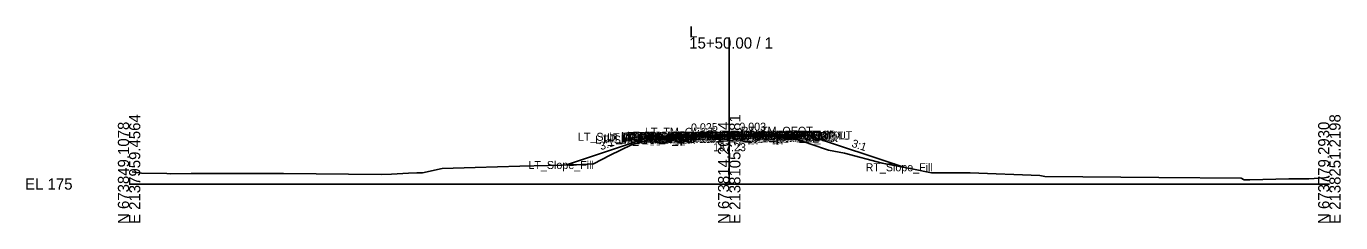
# Model space of a CAD drawing. Extents: x -26 to 5503, y -10 to 7033.
# Drawn here: x -25.7 to 302.8, y 6490.3 to 6539.5 of the extents above; entities that cross this region are included whole.
import ezdxf

# ---------------------------------------------------------------- set-up
doc = ezdxf.new("R2010")
doc.units = 0
for name, color, linetype in [('Default', 7, 'Continuous'), ('Exist CMT Pavement', 7, 'Continuous'), ('Exist Cross Section Cell', 7, 'Continuous'), ('Exist XS Center Line Elevation Label', 7, 'Continuous'), ('Exist XS Ground Line', 7, 'Continuous'), ('Prop CMT Pvmt Course 1', 7, 'Continuous'), ('Prop CMT Pvmt Course 1 Wedge', 7, 'Continuous'), ('Prop CMT Pvmt Course 2', 7, 'Continuous'), ('Prop CMT Pvmt Course 2 Wedge', 7, 'Continuous'), ('Prop CMT Pvmt Course 3', 7, 'Continuous'), ('Prop CMT Pvmt Course 3 Wedge', 7, 'Continuous'), ('Prop CMT Pvmt Surface', 7, 'Continuous'), ('Prop CMT Pvmt Surface Shoulder', 7, 'Continuous'), ('Prop CMT Pvmt Wedge Surface 1', 7, 'Continuous'), ('Prop CMT Pvmt Wedge Surface 2', 7, 'Continuous'), ('Prop CMT Pvmt Wedge Surface 3', 7, 'Continuous'), ('Prop CMT Shld Paved Course 1', 7, 'Continuous'), ('Prop CMT Shld Paved Course 2', 7, 'Continuous'), ('Prop CMT Shld Paved Course 3', 7, 'Continuous'), ('Prop CMT Slope Grass', 7, 'Continuous'), ('Prop CMT Subgrade Earthwork', 7, 'Continuous'), ('Prop XS Earthwork Shape', 7, 'Continuous'), ('Prop XS EOT Tick Mark', 7, 'Continuous'), ('Prop XS SE Text', 7, 'Continuous'), ('Prop XS Side Slope Text', 7, 'Continuous'), ('Prop XS Wedging', 7, 'Continuous')]:
    doc.layers.add(name, color=color, linetype=linetype)

msp = doc.modelspace()

# ---------------------------------------------------------------- linework, layer by layer
at = {"layer": 'Exist CMT Pavement'}
for points in [[(150, 6512.23), (148.67, 6512.21), (144, 6512.14), (139.33, 6512.06), (138, 6512.04)], [(150, 6512.23), (151.33, 6512.21), (155.98, 6512.12), (160.63, 6512.03), (161.96, 6512.01)]]:
    msp.add_lwpolyline(points, dxfattribs=at)
at = {"layer": 'Exist Cross Section Cell'}
for p, q in [((150, 6500), (150, 6536.71)), ((0, 6500), (150, 6500)), ((150, 6500), (300, 6500))]:
    msp.add_line(p, q, dxfattribs=at)
at = {"layer": 'Exist XS Ground Line'}
for p, q in [((129.99, 6511.06), (136, 6511.89)), ((136, 6511.89), (137.72, 6512.03)), ((137.72, 6512.03), (148.42, 6512.21)), ((148.42, 6512.21), (149.71, 6512.24)), ((149.71, 6512.24), (160.7, 6512.03)), ((160.7, 6512.03), (161.92, 6512.01)), ((161.92, 6512.01), (162.88, 6511.95)), ((162.88, 6511.95), (165.5, 6511.71)), ((165.5, 6511.71), (170.41, 6509.99)), ((120.28, 6507.27), (125.6, 6509.79)), ((125.6, 6509.79), (129.99, 6511.06)), ((170.41, 6509.99), (174.81, 6508.44)), ((174.81, 6508.44), (178.81, 6507.72)), ((111.8, 6504.85), (116.06, 6505.02)), ((116.06, 6505.02), (120.28, 6507.27)), ((178.81, 6507.72), (188.23, 6505.2)), ((188.23, 6505.2), (196.02, 6503.75)), ((0.73, 6503.08), (3.08, 6502.76)), ((3.08, 6502.76), (9.46, 6502.61)), ((9.46, 6502.61), (10.39, 6502.55)), ((10.39, 6502.55), (15.54, 6502.61)), ((15.54, 6502.61), (38.62, 6502.64)), ((38.62, 6502.64), (62.97, 6502.42)), ((62.97, 6502.42), (65.56, 6502.46)), ((65.56, 6502.46), (69.83, 6502.75)), ((69.83, 6502.75), (71.89, 6502.79)), ((71.89, 6502.79), (72.8, 6502.81)), ((72.8, 6502.81), (73.32, 6502.82)), ((73.32, 6502.82), (78.22, 6503.85)), ((78.22, 6503.85), (86.49, 6504.16)), ((86.49, 6504.16), (97.69, 6504.46)), ((97.69, 6504.46), (111.8, 6504.85)), ((196.02, 6503.75), (200.52, 6502.8)), ((200.52, 6502.8), (210.19, 6502.78)), ((210.19, 6502.78), (227.65, 6502.11)), ((227.65, 6502.11), (228.88, 6501.86)), ((228.88, 6501.86), (257.37, 6501.62)), ((298.77, 6501.57), (299.61, 6501.73)), ((299.61, 6501.73), (300, 6501.97)), ((257.37, 6501.62), (277.99, 6501.45)), ((277.99, 6501.45), (278.68, 6501.08)), ((278.68, 6501.08), (280.13, 6501.03)), ((280.13, 6501.03), (289.85, 6501.34)), ((289.85, 6501.34), (294.9, 6501.28)), ((294.9, 6501.28), (298.77, 6501.57))]:
    msp.add_line(p, q, dxfattribs=at)
at = {"layer": 'Prop CMT Pvmt Course 1'}
for points in [[(150, 6512.38), (138, 6512.08)], [(138, 6511.95), (150, 6512.25)], [(138, 6512.08), (138, 6511.83), (138, 6511.83), (138, 6511.95)], [(150, 6512.25), (150, 6512.38)], [(150, 6512.38), (162, 6512.34)], [(150, 6512.25), (150, 6512.38)], [(161.96, 6512.22), (150, 6512.25)], [(161.96, 6512.09), (161.96, 6512.22)], [(162, 6512.09), (161.96, 6512.09)], [(162, 6512.34), (162, 6512.09)]]:
    msp.add_lwpolyline(points, dxfattribs=at)
at = {"layer": 'Prop CMT Pvmt Course 1 Wedge'}
for points in [[(150, 6512.25), (138, 6511.95)], [(150, 6512.25), (161.96, 6512.22)]]:
    msp.add_lwpolyline(points, dxfattribs=at)
at = {"layer": 'Prop CMT Pvmt Course 2'}
for points in [[(161.96, 6511.88), (161.96, 6512.09)], [(161.96, 6512.09), (162, 6512.09)], [(162, 6511.88), (161.96, 6511.88)], [(162, 6512.09), (162, 6511.88)]]:
    msp.add_lwpolyline(points, dxfattribs=at)
at = {"layer": 'Prop CMT Pvmt Course 2 Wedge'}
for points in [[(150, 6512.13), (138, 6511.83)], [(150, 6512.13), (161.96, 6512.09)]]:
    msp.add_lwpolyline(points, dxfattribs=at)
at = {"layer": 'Prop CMT Pvmt Course 3'}
for points in [[(138, 6511.62), (138, 6511.62), (138, 6511.29), (138, 6511.29)], [(138, 6511.29), (138, 6511.62)], [(161.96, 6511.88), (162, 6511.88)], [(161.96, 6511.55), (161.96, 6511.88)], [(162, 6511.55), (161.96, 6511.55)], [(162, 6511.88), (162, 6511.55)]]:
    msp.add_lwpolyline(points, dxfattribs=at)
at = {"layer": 'Prop CMT Pvmt Course 3 Wedge'}
for points in [[(150, 6511.92), (138, 6511.62)], [(150, 6511.92), (161.96, 6511.88)]]:
    msp.add_lwpolyline(points, dxfattribs=at)
at = {"layer": 'Prop CMT Pvmt Surface'}
for points in [[(150, 6512.38), (138, 6512.08)], [(150, 6512.38), (162, 6512.34)]]:
    msp.add_lwpolyline(points, dxfattribs=at)
at = {"layer": 'Prop CMT Pvmt Surface Shoulder'}
for points in [[(138, 6512.08), (133.12, 6511.95)], [(162, 6512.34), (166.78, 6512.33)]]:
    msp.add_lwpolyline(points, dxfattribs=at)
at = {"layer": 'Prop CMT Pvmt Wedge Surface 1'}
for points in [[(150, 6512.25), (138, 6511.95)], [(138, 6511.95), (138, 6512.08)], [(138, 6512.08), (138, 6512.08)], [(150, 6512.25), (161.96, 6512.22)], [(161.96, 6512.22), (161.96, 6512.34)], [(161.96, 6512.34), (162, 6512.34)]]:
    msp.add_lwpolyline(points, dxfattribs=at)
at = {"layer": 'Prop CMT Pvmt Wedge Surface 2'}
for points in [[(150, 6512.13), (138, 6511.83)], [(138, 6511.83), (138, 6512.08)], [(138, 6511.83), (138, 6511.83)], [(150, 6512.13), (161.96, 6512.09), (162, 6512.09)], [(162, 6512.09), (162, 6512.34)]]:
    msp.add_lwpolyline(points, dxfattribs=at)
at = {"layer": 'Prop CMT Pvmt Wedge Surface 3'}
for points in [[(138, 6511.62), (138, 6512.08)], [(150, 6511.92), (138, 6511.62)], [(138, 6511.62), (138, 6511.62)], [(150, 6511.92), (161.96, 6511.88), (162, 6511.88)], [(162, 6511.88), (162, 6512.34)]]:
    msp.add_lwpolyline(points, dxfattribs=at)
at = {"layer": 'Prop CMT Shld Paved Course 1'}
for points in [[(138, 6512.08), (133.12, 6511.95), (132.87, 6511.7)], [(132.87, 6511.7), (138, 6511.83)], [(138, 6511.83), (138, 6512.08)], [(162, 6512.34), (166.78, 6512.33), (167.03, 6512.08)], [(162, 6512.09), (162, 6512.34)], [(167.03, 6512.08), (162, 6512.09)]]:
    msp.add_lwpolyline(points, dxfattribs=at)
at = {"layer": 'Prop CMT Shld Paved Course 2'}
for points in [[(138, 6511.83), (132.87, 6511.7), (132.65, 6511.48)], [(132.65, 6511.48), (138, 6511.62)], [(138, 6511.62), (138, 6511.83)], [(162, 6512.09), (167.03, 6512.08), (167.24, 6511.87)], [(162, 6511.88), (162, 6512.09)], [(167.24, 6511.87), (162, 6511.88)]]:
    msp.add_lwpolyline(points, dxfattribs=at)
at = {"layer": 'Prop CMT Shld Paved Course 3'}
for points in [[(138, 6511.62), (132.65, 6511.48)], [(138, 6511.29), (138, 6511.62)], [(162, 6511.88), (167.24, 6511.87)], [(162, 6511.55), (162, 6511.88)], [(167.57, 6511.53), (162, 6511.55)], [(167.24, 6511.87), (167.24, 6511.87)], [(167.24, 6511.87), (167.57, 6511.53)], [(132.65, 6511.48), (132.31, 6511.14)], [(132.31, 6511.14), (138, 6511.29)], [(132.65, 6511.48), (132.65, 6511.48)]]:
    msp.add_lwpolyline(points, dxfattribs=at)
at = {"layer": 'Prop CMT Slope Grass'}
for points in [[(130.09, 6511.71), (109.3, 6504.78)], [(133.12, 6511.95), (130.09, 6511.71)], [(166.78, 6512.33), (169.82, 6512.13)], [(169.82, 6512.13), (193.63, 6504.2)]]:
    msp.add_lwpolyline(points, dxfattribs=at)
at = {"layer": 'Prop CMT Subgrade Earthwork'}
for points in [[(132.31, 6511.14), (131.62, 6511.83)], [(138, 6511.29), (138, 6512.04)], [(161.96, 6511.55), (161.96, 6512.01)], [(161.96, 6511.55), (162, 6511.55)], [(162, 6511.55), (167.57, 6511.53)], [(167.57, 6511.53), (168.27, 6512.23)], [(138, 6511.29), (132.31, 6511.14)], [(138, 6511.29), (138, 6511.29)]]:
    msp.add_lwpolyline(points, dxfattribs=at)
at = {"layer": 'Prop XS Earthwork Shape'}
for points in [[(129.99, 6511.06), (132.1, 6511.35), (131.62, 6511.83), (130.09, 6511.71), (109.3, 6504.78), (111.8, 6504.85), (116.06, 6505.02), (120.28, 6507.27), (125.6, 6509.79)], [(138, 6511.29), (138, 6512.04), (137.72, 6512.03), (136, 6511.89), (132.1, 6511.35), (132.31, 6511.14)], [(149.71, 6512.24), (150, 6512.23), (148.67, 6512.21)], [(162.88, 6511.95), (165.5, 6511.71), (166, 6511.54), (161.96, 6511.55), (161.96, 6512.01)], [(188.23, 6505.2), (193.63, 6504.2), (169.82, 6512.13), (168.27, 6512.23), (167.57, 6511.53), (166, 6511.54), (170.41, 6509.99), (174.81, 6508.44), (178.81, 6507.72)]]:
    msp.add_lwpolyline(points, close=True, dxfattribs=at)
at = {"layer": 'Prop XS EOT Tick Mark'}
for points in [[(138, 6512.08), (138, 6513.08)], [(162, 6512.34), (162, 6513.34)]]:
    msp.add_lwpolyline(points, dxfattribs=at)
at = {"layer": 'Prop XS Wedging'}
for p, q in [((138, 6513.08), (138, 6509.69)), ((162, 6513.34), (162, 6509.86))]:
    msp.add_line(p, q, dxfattribs=at)

# ---------------------------------------------------------------- texts
at = {"layer": 'Default'}
for s, height, p in [('LT_Sub_Trench_Out_DLT', 2, (112.19, 6510.83)), ('LT_Sub_Trench_Out', 2, (116.52, 6510.14)), ('LT_PS3_Shelf_Out', 2, (118.64, 6510.48)), ('LT_GS_OS_CTL', 2, (119.46, 6510.71)), ('LT_PS3_OEOP', 2, (122.89, 6510.48)), ('LT_PV_Sub_Tie_Out', 2, (122.95, 6511.04)), ('LT_PS2_OEOP', 2, (123.1, 6510.7)), ('LT_PS1_OEOP', 2, (123.93, 6510.95)), ('LT_PV1_OEEOP_Null', 2, (124.46, 6511.08)), ('LT_PV_EG_TestPt3', 2, (124.85, 6511.06)), ('LT_PV_OEEOP_EG', 2, (125.54, 6511.04)), ('LT_PV1_OEEOP_W', 2, (125.98, 6510.95)), ('LT_Sub_OEEOP', 2, (127.21, 6510.29)), ('LT_PV2_OEEOP', 2, (127.31, 6510.83)), ('LT_PV3_OEEOP', 2, (127.31, 6510.62)), ('LT_Sub_OEOT', 2, (128.08, 6510.29)), ('LT_PV2_OEOT', 2, (128.17, 6510.83)), ('LT_PV3_OEOT', 2, (128.17, 6510.62)), ('LT_PV1_OEOT', 2, (128.74, 6511.08)), ('LT_TM_OEOT', 2, (128.94, 6512.08)), ('LT_PV_EG_TestPt2', 2, (129.51, 6511.14)), ('LT_PV_EG_TestPt1', 2, (134.75, 6511.21)), ('RT_PV_EG_TestPt1', 2, (137.36, 6511.21)), ('PV_EPGL_EG', 2, (141.24, 6511.23)), ('RT_PV_EG_TestPt2', 2, (141.45, 6511.12)), ('PV2_PGL_W', 2, (142.02, 6511.13)), ('PV3_PGL_W', 2, (142.02, 6510.92)), ('PV1_PGL_W', 2, (142.58, 6511.25)), ('PV1_PGL', 2, (144.47, 6511.38)), ('RT_PV_EG_TestPt3', 2, (146.1, 6511.03)), ('RT_PV_Sub_Tie_Out', 2, (146.86, 6511.01)), ('RT_PV1_OEEOP_Null', 2, (148.37, 6511.34)), ('RT_Sub_Trench_Out_DLT', 2, (148.79, 6511.23)), ('RT_PV_OEEOP_EG', 2, (149.46, 6511.01)), ('RT_PV1_OEEOP_W', 2, (149.9, 6511.22)), ('RT_Sub_OEEOP', 2, (151.13, 6510.55)), ('RT_PV2_OEEOP', 2, (151.22, 6511.09)), ('RT_PV3_OEEOP', 2, (151.22, 6510.88)), ('RT_Sub_Trench_Out', 2, (151.73, 6510.53)), ('RT_Sub_OEOT', 2, (152.03, 6510.55)), ('RT_PV2_OEOT', 2, (152.13, 6511.09)), ('RT_PV3_OEOT', 2, (152.13, 6510.88)), ('RT_PV1_OEOT', 2, (152.69, 6511.34)), ('RT_TM_OEOT', 2, (152.9, 6512.34)), ('RT_PS3_Shelf_Out', 2, (153.17, 6510.87)), ('RT_PS2_OEOP', 2, (157.22, 6511.08)), ('RT_PS3_OEOP', 2, (157.42, 6510.87)), ('RT_PS1_OEOP', 2, (157.53, 6511.33)), ('RT_GS_OS_CTL', 2, (159.14, 6511.13)), ('LT_Slope_Fill', 2, (99.82, 6503.78)), ('RT_Slope_Fill', 2, (184.1, 6503.2)), ('-', 0.0001, (0, 6500))]:
    msp.add_text(s, height=height, dxfattribs=at).set_placement(p)
at = {"layer": 'Exist Cross Section Cell'}
for s, p in [('L', (140, 6536.71)), ('15+50.00 / 1', (140, 6533.91)), ('EL 175', (-26, 6498.6))]:
    msp.add_text(s, height=2.8, dxfattribs=at).set_placement(p)
for s, p in [('N 673849.1078', (0, 6490)), ('E 2137959.4564', (2.8, 6490)), ('N 673814.2004', (150, 6490)), ('E 2138105.3381', (152.8, 6490)), ('N 673779.2930', (300, 6490)), ('E 2138251.2198', (302.8, 6490))]:
    msp.add_text(s, height=2.8, rotation=90, dxfattribs=at).set_placement(p)
at = {"layer": 'Exist XS Center Line Elevation Label'}
msp.add_text('187.23', height=2, dxfattribs=at).set_placement((145.99, 6508.23))
at = {"layer": 'Prop XS SE Text'}
for s, rotation, p in [('0.025', 1.4321, (140.48, 6513.14)), ('0.003', 359.8281, (152.52, 6513.37))]:
    msp.add_text(s, height=2, rotation=rotation, dxfattribs=at).set_placement(p)
at = {"layer": 'Prop XS Side Slope Text'}
for rotation, p in [(18.4349, (117.94, 6508.45)), (341.5651, (180.44, 6509.38))]:
    msp.add_text('3:1', height=2, rotation=rotation, dxfattribs=at).set_placement(p)

doc.saveas('drawing.dxf')
